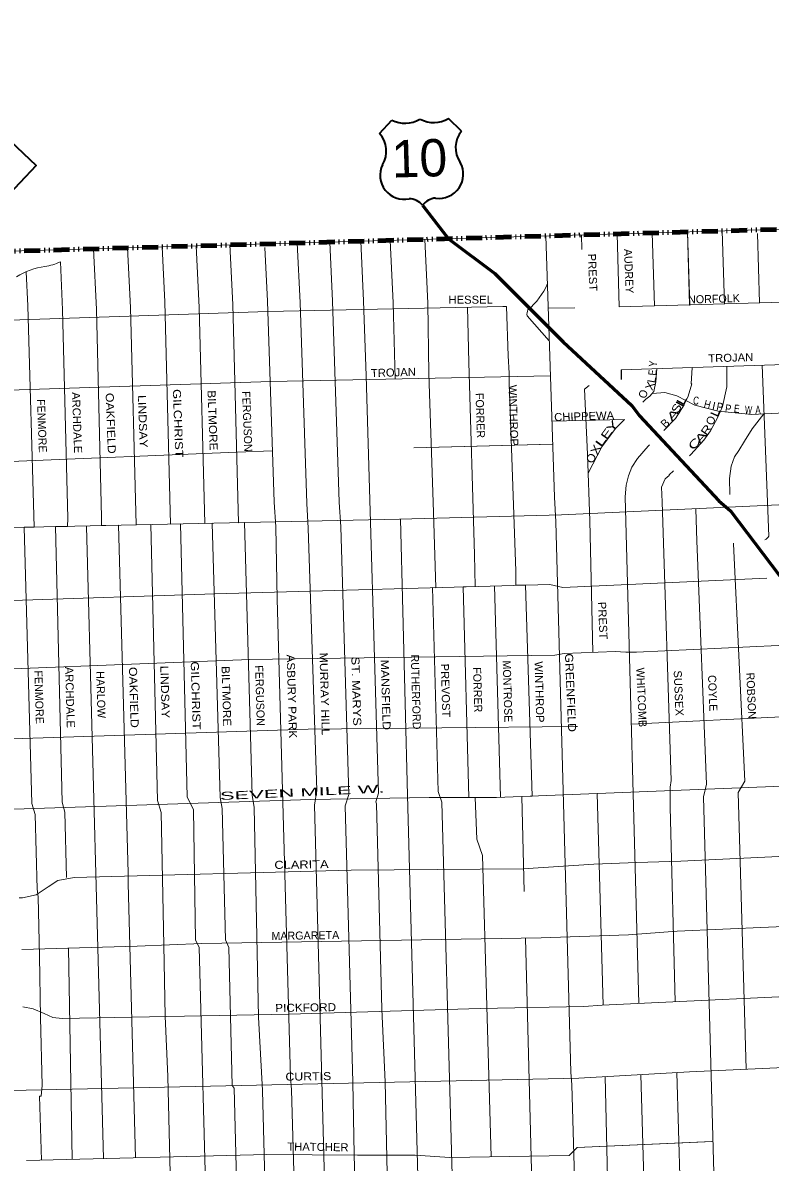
# Model space of a CAD drawing. Extents: x 34705 to 138605, y 34275 to 143551.
# Drawn here: x 53584 to 60584, y 132625 to 143301 of the extents above; entities that cross this region are included whole.
import ezdxf
from ezdxf.enums import TextEntityAlignment as Align

# ---------------------------------------------------------------- set-up
doc = ezdxf.new("R2010")
doc.units = 0
doc.header["$LTSCALE"] = 30
doc.linetypes.add('DASH_DOUBLE_DOT', pattern=[9.2, 5, -1.2, 0.3, -1.2, 0.3, -1.2])
for name, color, linetype, lineweight in [('1', 7, 'Continuous', 13), ('11', 7, 'Continuous', 13), ('51', 7, 'Continuous', 35), ('59', 7, 'DASH_DOUBLE_DOT', 106)]:
    doc.layers.add(name, color=color, linetype=linetype, lineweight=lineweight)

msp = doc.modelspace()

# ---------------------------------------------------------------- linework, layer by layer
at = {"layer": '1'}
for p, q in [((75780.8, 141796.99), (34922.9, 140631.57)), ((58816.06, 141313.09), (58819, 141175.38)), ((59149.36, 141322.6), (59169.39, 140638.51)), ((59479.01, 141332), (59499.03, 140648.19)), ((59809.77, 141341.43), (59829.78, 140657.91)), ((59809.77, 141341.43), (59829.96, 140651.92)), ((60135.32, 141350.72), (60155.33, 140667.47)), ((60466.36, 141326.92), (60485.38, 140677.17)), ((58504.79, 140626.3), (58753.64, 140630.75)), ((59169.39, 140638.51), (61143.85, 140696.51)), ((58308.41, 140556.8), (58514.89, 140320.43)), ((59188.11, 140049.59), (61167.99, 140114.8)), ((60508.74, 140093.71), (60570.87, 138491.87)), ((58539.75, 139567.46), (59220.61, 139585.38)), ((57246.05, 139319.6), (58546.84, 139352.84)), ((57246.05, 139319.6), (58542.75, 139352.73)), ((55587.65, 139277.3), (55922.3, 139291.12)), ((54181.19, 138581.55), (54340.1, 132659.59)), ((58000.45, 138023.92), (58057.13, 136043.97)), ((59283.65, 136728.46), (61462.5, 136833.81)), ((58964.48, 136079.63), (59019.25, 134097.15)), ((56909.61, 135470.12), (56909.66, 135465.42)), ((54011.97, 134630.95), (54047.35, 132652.24)), ((58291.55, 134725.15), (58352.77, 132429.39)), ((59708.86, 133464.8), (59746.84, 132165.25))]:
    msp.add_line(p, q, dxfattribs=at)
for points in [[(56749.23, 141254.13), (56775.76, 140696.32), (56799.66, 139992.62), (56914.46, 136084.12), (56890.56, 136001.52), (56895.36, 135982.42), (56947.96, 134058.12), (56976.66, 133378.32), (57034.32, 130811.67), (57106.26, 128105.82), (57130.16, 127465.72), (57195.07, 125477.54)], [(57025.45, 141262.01), (57053.26, 140677.12), (57071.58, 139963.45)], [(57350.18, 141271.28), (57378.66, 140672.42), (57388.26, 140011.72), (57431.26, 138716.92), (57451.91, 138008.03), (57421.15, 138008.69), (57474.36, 136098.52), (57507.86, 135997.92), (57871.27, 122928.9), (57837.21, 122947.63), (57938.6, 120227.09), (58104.41, 120232.58), (58141.77, 118928.03)], [(58482.93, 141303.59), (58501.06, 140739.32), (58563.26, 138855.62), (58577.66, 138625.82), (58716.36, 133469.22), (58725.96, 133349.52), (58759.46, 132146.82), (58754.66, 132041.52), (58792.96, 130796.92), (58773.86, 130758.62), (58940.46, 125579.92), (58922.56, 125484.22), (59115.44, 118962.33), (59098.57, 118742.9), (59064.82, 118377.17), (59080.91, 117690.79), (59156.14, 117419.97)], [(54246.06, 141182.73), (54273.06, 140614.92), (54320.86, 138669.02), (54322.1, 138590.72), (54479.12, 138592.92), (54569.66, 135336.22), (54569.66, 135235.62), (54638.99, 132667.09)], [(54564.78, 141191.83), (54591.36, 140632.92), (54645.74, 138596.52), (54783.67, 138599.94), (54844.46, 136015.22), (54880.36, 135901.52), (54904.26, 134657.32), (54916.26, 133993.42), (54941.95, 133427.98), (55043.19, 129286.89), (55082.56, 128098.3), (55088.19, 127997.03), (55103.06, 127346.12), (55197.83, 124499.41), (55154.04, 124420.38), (55337.23, 124320.76), (55239.16, 124138.32), (55131.46, 123946.92), (54981.96, 123635.92), (54922.16, 123402.62), (54904.26, 123199.22), (55003.63, 120123.87), (54839.31, 120121.19), (54896.95, 118237.91)], [(54889.8, 141201.1), (54914.26, 140686.72), (54968.6, 138603.14), (55061.09, 138605.94), (55124.76, 136049.42), (55182.16, 135924.92), (55201.36, 134709.12), (55234.86, 134637.32), (55306.29, 131956.82)], [(55207.47, 141210.16), (55234.86, 140634.12), (55289.47, 138610.37), (55358.09, 138611.86), (55431.06, 136041.02), (55450.16, 135939.32), (55483.66, 134709.12), (55512.36, 134637.32), (55545.86, 133343.62), (55565.06, 133319.72), (55593.76, 132089.52), (55598.27, 131963.53)], [(55524.2, 141219.19), (55550.66, 140662.82), (55602.87, 138616.78), (55659.85, 138618.07), (55732.46, 136063.82), (55751.66, 135948.92), (55791.27, 133984.99), (55828.16, 133296.92), (55899.96, 130543.32), (55970.16, 128063.92), (56053.15, 125448.68), (56150.85, 125450.37), (55480.55, 124242.82)], [(55852.16, 141194.12), (55876.06, 140691.52), (55938.26, 138807.82), (55952.66, 138578.02), (55965.63, 137901.03), (56091.36, 133421.42), (56100.96, 133301.72), (56134.46, 132099.02), (56129.66, 131993.72), (56167.96, 130749.12), (56148.86, 130710.82), (56316.45, 125453.22)], [(56154.44, 141237.17), (56180.96, 140679.52), (56243.16, 138795.82), (56257.56, 138566.02), (56339.36, 136106.42), (56315.46, 135968.82), (56454.98, 130811.67), (56449.35, 130665.38), (56608.84, 125458.27), (56475.81, 125455.97), (56533.31, 123667.84), (56646.29, 123600.93), (56657.47, 122841.77), (56748.28, 120175.73), (56801.25, 120177.35), (56883.33, 117658.39)], [(56459.6, 141245.87), (56485.96, 140691.52), (56548.16, 138807.82), (56562.56, 138578.02), (56638.36, 136070.52), (56602.46, 135962.92), (56674.26, 133374.22), (56686.16, 132698.32), (56739.96, 130670.52), (56896.05, 125467.55), (56799.13, 125464.31), (56861.36, 123485.08), (56958.51, 123431.41), (57053.57, 120209.74), (57129.77, 120212.04), (57205.7, 117664.26)], [(53935.67, 141061.93), (53957.16, 140610.12), (54004.96, 138659.42), (54003.88, 138582.66), (53888.96, 138580.39), (53952.36, 135996.72), (53977.46, 135904.52), (53993.77, 135291.43)], [(53616.53, 140968.63), (53631.76, 140648.42), (53689.38, 138576.14), (53597.22, 138575.05), (53670.06, 135987.22), (53698.76, 135881.92), (53717.86, 135183.02), (53727.46, 135111.22), (53741.86, 134555.92), (53751.36, 133981.52), (53765.76, 133344.82), (53756.16, 133244.32), (53741.86, 133244.32), (53758.12, 132644.98)], [(53368.56, 140511.48), (55879.96, 140597.32), (58080.54, 140643.85), (58115.74, 140642.42)], [(57747.92, 140636.82), (57761.46, 140117.12), (57814.06, 138319.52), (57821.43, 138017.69), (57708.54, 138015.71), (57762.55, 136042.52), (57820.23, 136042.52), (57835.66, 135650.92), (57888.26, 135497.72), (57970, 132674.93)], [(58115.74, 140642.42), (58129.96, 140179.22), (58139.56, 140016.52), (58139.56, 139935.12), (58201.76, 138161.62), (58202.73, 138030.03), (58292.15, 138031.04), (58355.42, 136055.69), (58257.69, 136051.85), (58280.53, 135162.62)], [(60179.26, 140079.92), (60179.26, 139888.42), (60136.16, 139706.52), (60136.16, 139706.52), (60093.16, 139606.02), (60093.16, 139606.02), (60026.16, 139476.82), (60026.16, 139476.82), (59963.86, 139390.62), (59963.86, 139390.62), (59839.46, 139256.62), (59839.46, 139256.62), (59827.15, 139244.89)], [(53359.98, 139856.3), (55906.13, 139940.13), (58521.82, 139992.46)], [(59523.29, 140060.63), (59514.06, 139936.32), (59494.96, 139845.42), (59494.96, 139845.42), (59456.66, 139802.32), (59456.66, 139802.32), (59418.36, 139773.62), (59418.36, 139773.62), (59418.36, 139773.62), (59418.36, 139773.62), (59390.51, 139747.1)], [(59480.29, 139828.91), (59597.98, 139835.45), (59708.44, 139806.37), (59877.05, 139719.13), (60097.98, 139660.97), (60411.93, 139631.89), (61150.3, 139666.79), (61220.07, 139748.21), (62853.01, 139809.8), (63790.47, 139854.26), (63792.81, 139729.87), (67294.18, 139829.63), (69631.39, 139881.97), (73731.67, 140014.28), (74283.99, 140031.73), (74481.67, 140025.91), (74586.32, 140008.46), (74708.41, 139991.02), (74882.83, 139927.04), (75039.81, 139857.25), (75214.22, 139735.12), (75359.57, 139624.62), (75516.55, 139455.96)], [(59853.86, 140070.32), (59844.26, 139917.22), (59849.06, 139917.22), (59815.56, 139802.32), (59815.56, 139802.32), (59777.26, 139725.72), (59777.26, 139720.92), (59695.96, 139591.72), (59695.96, 139591.72), (59586.45, 139482.11)], [(58888.69, 139902.84), (58845.36, 139868.12), (58873.58, 139258.41), (58896.08, 138633.87), (58922.68, 137403.33)], [(59220.69, 139585.3), (59217.36, 139582.12), (59217.36, 139582.12), (59136.06, 139500.72), (59136.06, 139500.72), (59006.86, 139328.42), (59006.86, 139328.42), (58879.93, 139082.06)], [(60524.69, 139637.22), (60413.76, 139495.92), (60341.96, 139381.02), (60289.26, 139294.92), (60251.06, 139232.62), (60217.56, 139146.52), (60217.56, 139146.52), (60203.16, 139031.62), (60203.16, 139031.62), (60207.35, 138881.1)], [(59453.93, 139345.24), (59442.26, 139333.22), (59442.26, 139333.22), (59341.86, 139218.32), (59289.16, 139136.92), (59289.16, 139136.92), (59255.66, 139055.52), (59255.66, 139055.52), (59236.56, 138969.42), (59226.96, 138859.32), (59226.96, 138859.32), (59353.26, 134112.63)], [(53407.25, 139191.2), (53471.54, 139189.89), (55585.98, 139277.23)], [(59677.51, 139102.33), (59638.46, 139065.12), (59638.46, 139060.32), (59600.26, 139026.82), (59566.76, 138950.22), (59566.76, 138950.22), (59571.56, 138811.42), (59571.56, 138811.42), (59657.66, 136200.22), (59648.06, 136137.92), (59648.06, 135951.32), (59692.62, 134128.36)], [(50738.64, 138513.12), (57112.52, 138649.02), (58629.96, 138689.73), (63786.92, 138928.18), (63887.95, 138948.95), (67307.74, 138988.33)], [(59887.36, 138743.22), (59896.96, 138446.42), (59987.86, 136166.72), (59959.06, 136047.02), (60065.39, 132185.79)], [(57120.4, 138649.23), (57187.26, 136063.82), (57293.05, 132150.77), (57306.86, 131438.52), (57482.08, 125487.13)], [(60240.91, 138426.05), (60241.46, 138418.92), (60241.46, 138418.92), (60346.76, 136195.42), (60284.46, 136090.12), (60359.06, 133496.07)], [(53453.47, 137889.76), (53487.53, 137887.14), (55382.88, 137951.12), (58519.5, 138038.35), (58641.59, 138009.27), (60552.84, 138098.35)], [(53493.37, 137247.58), (55711.36, 137334.64), (56560.19, 137346.27), (58566.01, 137375.35), (58653.22, 137392.8), (59132.32, 137411.52), (59231.7, 137404.43), (59333.45, 137404.43), (60923.56, 137480.03), (61062.26, 137489.13)], [(53488.97, 136591.27), (56257.87, 136681.82), (58761.09, 136708.21), (58778.75, 136706.01)], [(35050.01, 135441.89), (38867.68, 135617.88), (40146.22, 135653.27), (40348.36, 135643.16), (42072.86, 135638.1), (42926.9, 135633.05), (44579.39, 135678.54), (51671.96, 135890.86), (53501.32, 135931.3), (56282, 136022.29), (57388.72, 136042.52), (58020.4, 136042.52), (61877.48, 136194.17), (62342.4, 136219.45), (65279.74, 136335.71), (66593.65, 136340.77), (68808.33, 136381.21), (71284.55, 136401.43), (76864.35, 136528)], [(53550.94, 135101.37), (53582.01, 135101.37), (53709.91, 135130.45), (53820.38, 135206.05), (53913.4, 135264.21), (54064.57, 135293.29), (56659.03, 135361.62), (58269.5, 135373.26), (58933.73, 135416.88), (59334.89, 135434.33), (59747.68, 135445.96), (62439.54, 135573.91), (62456.11, 135574.75)], [(53573.66, 134618.55), (54656.13, 134649.19), (55260.78, 134672.45), (58438.1, 134727.7), (59256.06, 134755.82), (59712.8, 134788.77), (61852.33, 134881.83), (63031.64, 134946.77)], [(53584.37, 134080.29), (53680.84, 134063.25), (53785.5, 134016.72), (53866.89, 133981.83), (53954.1, 133970.2), (56078.13, 134013.12), (57866.77, 134063.76), (58839.26, 134082.14), (59009.31, 134096.69), (61393.03, 134207.19), (62695.36, 134265.35), (63615.75, 134310.76)], [(48198.29, 133162.97), (49942.48, 133199.59), (53326.19, 133292.64), (58792.75, 133413.32), (59827.63, 133471.48), (61398.85, 133544.18), (62741.87, 133608.16), (63962.8, 133660.5), (64165.31, 133663.7)], [(59037.76, 133427.09), (59066.22, 132205.63), (59329.66, 122906.03)], [(59371.01, 133445.82), (59693.86, 122254.12), (59598.26, 122056.72), (59562.36, 121931.12), (59610.86, 120282.15), (59746.91, 120287.31), (59823.66, 117686.56)], [(53617.43, 132641.45), (55869.79, 132697.99), (56718.63, 132692.17), (57259.32, 132692.17), (57584.91, 132668.91), (58699.73, 132686.35), (58775.31, 132761.96), (60047.99, 132817.62)], [(53617.43, 132641.45), (55869.79, 132697.99), (56718.63, 132692.17), (57259.32, 132692.17), (57584.91, 132668.91), (58699.73, 132686.35), (58775.31, 132761.96), (60038.38, 132817.2)]]:
    msp.add_lwpolyline(points, dxfattribs=at)
for centre, radius, start, end in [((53743.68, 141438.86), 423.01, 276.46777, 296.99226), ((53905.88, 140286.35), 741.1, 98.89147, 120.9842), ((57899.46, 141107.43), 648.28, 309.93236, 337.24536), ((58379.53, 140574.52), 73.3, 150.75593, 193.99424), ((60503.5, 138526.65), 75.94, 294.76497, 332.69107)]:
    msp.add_arc(centre, radius, start, end, dxfattribs=at)
at = {"layer": '11', "lineweight": 25}
msp.add_line((59188.11, 140049.59), (59189.02, 139958.77), dxfattribs=at)
at = {"layer": '51'}
for p, q in [((56923.36, 142264.4), (57039.19, 142389.51)), ((57694.1, 142286.81), (57571.2, 142404.98))]:
    msp.add_line(p, q, dxfattribs=at)
msp.add_lwpolyline([(52758.41, 141937.09), (53219.96, 142426.26), (53709.13, 141964.72), (53247.59, 141475.55)], close=True, dxfattribs=at)
at = {"layer": '51', "lineweight": 60}
msp.add_lwpolyline([(57328.6, 141592.26), (57571.5, 141277.59), (58004.21, 140952.96), (58644, 140312.96), (59287.28, 139714.93), (59360.7, 139617), (60101.88, 138823.12), (60211.13, 138727.83), (62487.11, 135721.94), (62689.88, 135526.09), (63165.36, 134994.51), (64305.09, 133644.57), (67189.39, 129467.1), (67720.8, 128865.58), (68108.86, 128381.22), (68864.02, 127255.1), (69010.86, 127136.19), (69262.58, 126891.39), (69647.16, 126779.47), (69954.82, 126695.54)], dxfattribs=at)
at = {"layer": '51'}
for centre, radius, start, end in [((57163.68, 142627.67), 268.73, 242.40256, 301.46889), ((57433.08, 142635.5), 268.73, 241.42362, 300.92744), ((56748.15, 142098.92), 241, 328.08598, 43.36339), ((57878.63, 142131.78), 241, 139.96661, 215.24402), ((57157.4, 141873.59), 226.89, 154.43005, 281.56253), ((57483.16, 141883.06), 226.89, 261.76747, 28.89995), ((57200.89, 141483.7), 167.61, 40.36594, 89.32063), ((57462.39, 141491.3), 167.61, 94.00937, 142.96406)]:
    msp.add_arc(centre, radius, start, end, dxfattribs=at)
at = {"layer": '59'}
msp.add_lwpolyline([(131989.06, 109708.72), (126856.28, 120352.83), (127983.73, 120601.28), (129321.71, 120998.46), (130612.42, 121494.12), (133722.19, 123216.65), (134563.84, 124776.42), (136438.38, 130047.1), (136736.54, 131235.05), (136773.12, 131974.15), (125584.57, 138103.26), (128512.62, 143301.1), (34921.35, 140631.52)], dxfattribs=at)

# ---------------------------------------------------------------- texts
at = {"layer": '11'}
for s, rotation, p in [('AUDREY', 272.294, (59222.64, 140972.6)), ('NORFOLK', 1.705, (60058.5, 140677.3)), ('L', 80.404, (59510.76, 139950.3)), ('FENMORE', 272.169, (53725.92, 139523.04)), ('FERGUSON', 272.171, (55648.82, 139564.85)), ('FORRER', 271.82, (57830.91, 139620.2)), ('O', 69.398, (59429.48, 139810.06)), ('I', 348.326, (60049.32, 139674.14)), ('B', 44.137, (59626.1, 139522.36)), ('RUTHERFORD', 271.644, (57228.16, 137029.79)), ('MONTROSE', 271.643, (58087.08, 137035.71)), ('FENMORE', 271.685, (53699.69, 136981.42)), ('HARLOW', 271.682, (54278.26, 137004.41)), ('FERGUSON', 271.685, (55767.86, 136995.92)), ('FORRER', 271.642, (57806.92, 137050.35)), ('WHITCOMB', 272.38, (59342.04, 136978.99)), ('ROBSON', 272.399, (60369.9, 136993.79)), ('COYLE', 272.4, (60008.59, 137018.18)), ('MARGARETA', 0.867, (56230.79, 134711.75))]:
    msp.add_text(s, height=75, rotation=rotation, dxfattribs=at).set_placement(p, align=Align.CENTER)
for s, rotation, width, p in [('PREST', 272.4, 1.05, (58883.31, 140960.82)), ('TROJAN', 1.794, 1.05, (60216.03, 140125.37)), ('Y', 84.643, 0.85, (59524.07, 140102.15)), ('TROJAN', 1.794, 1.05, (57056.12, 139987.56)), ('E', 84.643, 0.8, (59518.62, 140019.99)), ('GILCHRIST', 272.171, 1.2, (55001.07, 139546.61)), ('WINTHROP', 271.818, 1.05, (58142.27, 139620.89)), ('X', 69.398, 1.15, (59493.72, 139886.05)), ('ARCHDALE', 272.169, 1.05, (54054.78, 139552.83)), ('OAKFIELD', 272.172, 1.15, (54370.6, 139546.84)), ('LINDSAY', 272.172, 1.15, (54670.52, 139564.79)), ('BILTMORE', 272.171, 1.1, (55324.46, 139574.17)), ('L', 61.378, 1.5, (59786.73, 139745.92)), ('C', 354.983, 0.75, (59886.45, 139723.43)), ('H', 345.458, 0.85, (59986.45, 139688.25)), ('CHIPPEWA', 1.794, 1.05, (58842.7, 139577.59)), ('A', 48.298, 1.75, (59701.17, 139603.08)), ('S', 61.378, 1.3, (59738.91, 139670.95)), ('I', 61.378, 1.45, (59768.67, 139712.09)), ('L', 66.023, 1.35, (60103.25, 139635.13)), ('P', 349.268, 0.9, (60105.66, 139666.34)), ('P', 351.932, 0.85, (60185.55, 139648.85)), ('E', 355.115, 0.8, (60268.24, 139647.56)), ('W', 355.115, 0.65, (60377.49, 139636.5)), ('A', 1.126, 0.75, (60470.48, 139637.1)), ('Y', 50.957, 1.65, (59135.47, 139496.78)), ('Y', 50.957, 1.65, (59136.19, 139496.77)), ('O', 66.023, 1.05, (60061.64, 139559.58)), ('E', 54.194, 1.5, (59080.6, 139428.19)), ('A', 49.116, 1.7, (59962.72, 139392.49)), ('R', 55.39, 1.35, (60016.83, 139465.43)), ('X', 62.691, 1.3, (58982.59, 139285.43)), ('L', 54.194, 1.75, (59027.06, 139357.78)), ('C', 49.116, 1.55, (59901.01, 139332.47)), ('O', 62.691, 1.15, (58940.37, 139203.93)), ('PREST', 272.4, 1.05, (58979, 137698.4)), ('GILCHRIST', 271.685, 1.2, (55166.35, 136995.9)), ('ASBURY PARK', 271.642, 1.1, (56066.51, 136988.52)), ('MURRAY HILL', 271.642, 1.15, (56373.95, 137011.39)), ('ST. MARYS', 271.644, 1.2, (56670.7, 137037.08)), ('MANSFIELD', 271.643, 1.15, (56946.07, 137002.84)), ('WINTHROP', 271.644, 1.05, (58385.32, 137029.84)), ('GREENFIELD', 272.4, 1.15, (58677.21, 137022.8)), ('ARCHDALE', 271.683, 1.05, (53988.45, 136979.62)), ('OAKFIELD', 271.685, 1.15, (54586.59, 136979.03)), ('LINDSAY', 271.685, 1.15, (54878.94, 137029.67)), ('BILTMORE', 271.684, 1.1, (55453.72, 136990.47)), ('PREVOST', 271.643, 1.05, (57506.43, 137043.72)), ('SUSSEX', 272.398, 1.05, (59689, 137018.26)), ('SEVEN MILE W.', 2.633, 2.05, (56202.46, 136053.56)), ('CLARITA', 0.868, 1.2, (56194.85, 135376.59)), ('PICKFORD', 0.866, 1.1, (56233.82, 134036.44)), ('CURTIS', 0.864, 1.15, (56258.95, 133391.35)), ('THATCHER', 359.199, 1.05, (56347.89, 132730.46))]:
    msp.add_text(s, height=75, rotation=rotation, dxfattribs=dict(at, width=width)).set_placement(p, align=Align.CENTER)
at = {"layer": '11', "width": 1.05}
msp.add_text('HESSEL', height=75, dxfattribs=at).set_placement((57778.62, 140668.83), align=Align.CENTER)
at = {"layer": '51'}
msp.add_text('10', height=350, rotation=1.665, dxfattribs=at).set_placement((57303.52, 141857.7), align=Align.CENTER)

doc.saveas('drawing.dxf')
